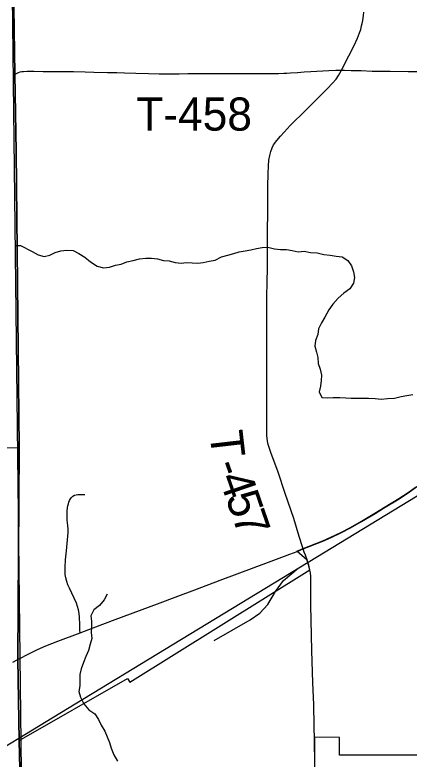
# Model space of a CAD drawing. Extents: x -7.5 to 53.5, y 0 to 22.
# Drawn here: x 4.57 to 5.246, y 17.086 to 18.362 of the extents above; entities that cross this region are included whole.
import ezdxf

# ---------------------------------------------------------------- set-up
doc = ezdxf.new("R2010")
doc.units = 0
for name, color, linetype in [('GM_X_Corporation', 7, 'Continuous'), ('GM_X_Minor_River', 7, 'Continuous'), ('GM_X_Rail_Line', 7, 'Continuous'), ('GM_X_State_Route', 7, 'Continuous'), ('GM_X_Township_Road', 7, 'Continuous'), ('GM_X_Township_Road_Text', 7, 'Continuous'), ('SH_Data', 7, 'Continuous')]:
    doc.layers.add(name, color=color, linetype=linetype)

msp = doc.modelspace()

# ---------------------------------------------------------------- linework, layer by layer
at = {"layer": 'GM_X_Corporation'}
for points in [[(4.6087, 14.5302), (4.6021, 15.6139), (4.594, 15.8096), (4.5873, 16.3533), (4.5872, 16.3635), (4.5826, 16.8462), (4.5822, 16.8992), (4.577, 17.1178), (4.5749, 17.2575), (4.5771, 17.6201), (4.5718, 18.1276), (4.5696, 18.2604), (4.5565, 19.1354), (5.0411, 19.1401), (6.0424, 19.1527), (6.0433, 19.1527), (6.5522, 19.1561), (7.544, 19.1455), (8.414, 19.1709), (8.5159, 19.1718), (8.9, 19.1887), (8.9, 20.9), (2.1, 20.9), (2.1, 14.1)], [(8.9, 14.1), (8.9, 19.1887), (8.5159, 19.1718), (8.414, 19.1709), (7.544, 19.1455), (6.5522, 19.1561), (6.0433, 19.1527), (6.0424, 19.1527), (5.0411, 19.1401), (4.5565, 19.1354), (4.5696, 18.2604), (4.5718, 18.1276), (4.5771, 17.6201), (4.5749, 17.2575), (4.577, 17.1178), (4.5822, 16.8992), (4.5826, 16.8462), (4.5872, 16.3635), (4.5873, 16.3533), (4.594, 15.8096), (4.6021, 15.6139), (4.6087, 14.5302)], [(4.1153, 17.6257), (4.5771, 17.6201), (4.5749, 17.2575), (4.577, 17.1178), (4.7631, 17.2246), (4.767, 17.2178), (5.0754, 17.4108), (5.0733, 17.4191), (5.0708, 17.4275), (5.0534, 17.4429), (5.064, 17.447), (5.0976, 17.4601), (5.1118, 17.4664), (5.1287, 17.4746), (5.1452, 17.4833), (5.1642, 17.4942), (5.1871, 17.508), (5.2017, 17.5167), (5.2283, 17.5331), (5.244, 17.5434), (5.2567, 17.5523)], [(5.4065, 17.093), (5.1262, 17.0931), (5.1262, 17.1234), (5.0833, 17.1238), (5.0837, 16.9694)]]:
    msp.add_lwpolyline(points, dxfattribs=at)
at = {"layer": 'GM_X_Minor_River'}
for points in [[(4.5699, 17.9665), (4.5794, 17.9668), (4.5997, 17.9567), (4.6099, 17.951), (4.6198, 17.9478), (4.6296, 17.9504), (4.6391, 17.9545), (4.6486, 17.9578), (4.6589, 17.9585), (4.6699, 17.958), (4.6797, 17.953), (4.6895, 17.9468), (4.6993, 17.9388), (4.711, 17.9311), (4.7215, 17.9283), (4.7318, 17.9298), (4.7424, 17.9331), (4.7519, 17.9345), (4.7618, 17.9386), (4.7724, 17.9408), (4.7835, 17.9437), (4.7941, 17.9451), (4.8039, 17.945), (4.8145, 17.9438), (4.8248, 17.9411), (4.8346, 17.9402), (4.8448, 17.9375), (4.8547, 17.9366), (4.8641, 17.9377), (4.874, 17.9368), (4.8835, 17.9367), (4.8929, 17.9374), (4.9032, 17.94), (4.9131, 17.9418), (4.9241, 17.9474), (4.9351, 17.9503), (4.945, 17.9533), (4.9545, 17.9558), (4.9644, 17.9576), (4.9746, 17.9594), (4.9841, 17.9616), (4.9936, 17.9634), (5.0038, 17.9637), (5.0148, 17.961), (5.025, 17.9597), (5.0353, 17.96), (5.0451, 17.958), (5.0553, 17.956), (5.0659, 17.9571), (5.0765, 17.9547), (5.0883, 17.9542), (5.0996, 17.9511), (5.1102, 17.9502), (5.1208, 17.9486), (5.1307, 17.9474), (5.1409, 17.9412), (5.1469, 17.9317), (5.1502, 17.9214), (5.152, 17.9119), (5.1504, 17.9021), (5.1439, 17.8923), (5.134, 17.8848), (5.1244, 17.8765), (5.1152, 17.8664), (5.1079, 17.8562), (5.101, 17.8441), (5.0956, 17.834), (5.0906, 17.8241), (5.089, 17.8143), (5.0855, 17.8041), (5.0843, 17.7939), (5.0869, 17.784), (5.0891, 17.7745), (5.0901, 17.7646), (5.0931, 17.7547), (5.0953, 17.7445), (5.0948, 17.735), (5.094, 17.7255), (5.0916, 17.7157), (5.0961, 17.7062), (5.1063, 17.7053), (5.1158, 17.706), (5.1272, 17.7059), (5.137, 17.7054), (5.1465, 17.7049), (5.1567, 17.7052), (5.1764, 17.705), (5.1874, 17.7046), (5.198, 17.7033), (5.2086, 17.7044), (5.2208, 17.705), (5.2322, 17.7076), (5.2417, 17.7094), (5.2523, 17.7112)], [(4.7279, 17.3689), (4.7229, 17.3591), (4.7149, 17.3493), (4.7053, 17.3418), (4.6999, 17.332), (4.7014, 17.3225), (4.7013, 17.3131), (4.7005, 17.3032), (4.7019, 17.2929), (4.6988, 17.2831), (4.696, 17.2725), (4.6914, 17.2619), (4.6875, 17.2517), (4.6837, 17.2412), (4.6813, 17.2313), (4.6812, 17.2215), (4.6811, 17.212), (4.6795, 17.2018), (4.6825, 17.1922), (4.6881, 17.1808), (4.6967, 17.1705), (4.7069, 17.164), (4.7133, 17.1541), (4.7177, 17.1445), (4.7241, 17.1339), (4.7278, 17.1243), (4.7323, 17.1144), (4.7352, 17.1049), (4.7393, 17.0935), (4.746, 17.0825)]]:
    msp.add_lwpolyline(points, dxfattribs=at)
at = {"layer": 'GM_X_Rail_Line'}
for points in [[(4.5767, 17.1219), (4.6471, 17.1649), (4.8554, 17.2917), (5.0726, 17.4239), (5.2728, 17.5456)], [(4.9114, 17.2896), (4.9735, 17.3249), (4.9899, 17.3362), (5.0034, 17.3512), (5.0168, 17.3736), (5.0302, 17.3923), (5.0555, 17.4135)], [(4.5236, 17.0903), (4.5767, 17.1219)]]:
    msp.add_lwpolyline(points, dxfattribs=at)
at = {"layer": 'GM_X_State_Route'}
for points in [[(5.0537, 17.4423), (5.0642, 17.4464), (5.0978, 17.4596), (5.112, 17.4659), (5.1289, 17.474), (5.1454, 17.4828), (5.1644, 17.4936), (5.1873, 17.5074), (5.2019, 17.5162), (5.2285, 17.5326), (5.2442, 17.5428), (5.2569, 17.5518), (5.2609, 17.5548), (5.2686, 17.561)], [(4.5751, 17.257), (4.5948, 17.2672), (4.6089, 17.2739), (4.6231, 17.2801), (4.6433, 17.2881), (4.6815, 17.3025), (4.7042, 17.3111), (4.7419, 17.3254), (4.8146, 17.3525), (4.8494, 17.3656), (4.8784, 17.3765), (4.922, 17.3929), (5.0091, 17.4255), (5.0411, 17.4374), (5.0537, 17.4423)], [(4.5663, 17.2522), (4.5739, 17.2564), (4.5751, 17.257)]]:
    msp.add_lwpolyline(points, dxfattribs=at)
at = {"layer": 'GM_X_Township_Road'}
for points in [[(5.1301, 18.2671), (5.1327, 18.2726), (5.1357, 18.279), (5.1422, 18.2918), (5.1507, 18.3084), (5.1573, 18.3225), (5.1608, 18.3312), (5.1628, 18.3371), (5.1644, 18.3432), (5.1654, 18.3471), (5.1664, 18.3526), (5.1677, 18.3613), (5.1683, 18.3666)], [(4.5698, 18.2599), (4.5735, 18.2623), (4.5758, 18.2634), (4.5787, 18.2644), (4.5817, 18.265), (4.5848, 18.2653), (4.5909, 18.2655), (4.6026, 18.2654), (4.6184, 18.2653), (4.6365, 18.2651), (4.6554, 18.265), (4.6704, 18.2648), (4.6902, 18.2647), (4.7052, 18.2642), (4.7287, 18.2635), (4.7449, 18.2631), (4.7577, 18.2627), (4.7771, 18.2621), (4.7987, 18.2615), (4.8172, 18.2613), (4.8265, 18.2612), (4.8513, 18.2613), (4.8664, 18.2614)], [(4.8664, 18.2614), (4.8855, 18.2615), (4.9072, 18.2616), (4.932, 18.2617), (4.9538, 18.2618), (4.9661, 18.2616), (4.9909, 18.2616), (5.0033, 18.2616), (5.0126, 18.2617), (5.0219, 18.2617), (5.0311, 18.262), (5.0362, 18.2624)], [(5.0088, 17.6117), (5.0073, 17.6155), (5.0043, 17.6256), (5.0029, 17.6314), (5.0016, 17.6409), (5.0016, 17.661), (5.0016, 17.6919), (5.0018, 17.731), (5.0019, 17.7547), (5.0019, 17.7935), (5.0019, 17.8774), (5.0023, 17.9049), (5.0027, 17.9276), (5.003, 17.9463), (5.003, 17.9572), (5.003, 17.9881), (5.0033, 18.0272), (5.0037, 18.0683), (5.0041, 18.0898), (5.0044, 18.1032), (5.0052, 18.1133), (5.0069, 18.1211), (5.0086, 18.1279), (5.0108, 18.1341), (5.0135, 18.1393), (5.0188, 18.1467), (5.0254, 18.1542), (5.0315, 18.1613), (5.0421, 18.1726), (5.0684, 18.1989), (5.0926, 18.2229), (5.1059, 18.2359), (5.1145, 18.2449), (5.1205, 18.252), (5.1246, 18.258), (5.1271, 18.262), (5.1301, 18.2671)], [(5.0362, 18.2624), (5.0422, 18.2628), (5.0542, 18.2636), (5.066, 18.2644), (5.0775, 18.2652), (5.1082, 18.2667), (5.1204, 18.2672), (5.1301, 18.2671)], [(5.1301, 18.2671), (5.135, 18.2671), (5.1462, 18.2669), (5.1634, 18.2666), (5.1823, 18.2659), (5.1863, 18.2659)], [(5.1863, 18.2659), (5.2133, 18.2658), (5.2444, 18.2652), (5.2816, 18.2649), (5.3406, 18.2643), (5.4183, 18.2635), (5.4555, 18.2634), (5.4897, 18.2638), (5.5052, 18.2636), (5.5145, 18.263), (5.5207, 18.2622), (5.5268, 18.261), (5.5327, 18.2592), (5.5385, 18.257), (5.5441, 18.2543), (5.5523, 18.2498), (5.5845, 18.2311), (5.6165, 18.2125), (5.6515, 18.1924), (5.7082, 18.1601), (5.7435, 18.1405), (5.7536, 18.1351)], [(5.0642, 17.4464), (5.063, 17.45), (5.0573, 17.468), (5.0481, 17.4986), (5.0335, 17.5417), (5.0213, 17.5784), (5.0088, 17.6117)], [(4.6815, 17.3025), (4.6813, 17.3075), (4.681, 17.3169), (4.6806, 17.3294), (4.68, 17.3356), (4.679, 17.3418), (4.6774, 17.3478), (4.6753, 17.3537), (4.6714, 17.3622), (4.6633, 17.3791), (4.6609, 17.3848), (4.6589, 17.3907), (4.6573, 17.3968), (4.6563, 17.4029), (4.6559, 17.4091), (4.6559, 17.4154), (4.6568, 17.4278), (4.6584, 17.4434), (4.6603, 17.462), (4.6613, 17.4744), (4.6613, 17.4806), (4.6608, 17.4867), (4.6597, 17.4959), (4.6594, 17.5021), (4.6595, 17.5114), (4.6601, 17.5176), (4.6607, 17.5206), (4.6615, 17.5237), (4.6625, 17.5266), (4.6637, 17.5295), (4.6653, 17.5322), (4.6671, 17.5346), (4.6694, 17.5367), (4.672, 17.5384), (4.6749, 17.5394), (4.678, 17.5398), (4.6809, 17.5401), (4.6841, 17.5401), (4.6898, 17.54)], [(5.0707, 17.4278), (5.068, 17.4358), (5.0661, 17.4411), (5.0642, 17.4464)], [(5.0756, 17.4103), (5.0752, 17.4121), (5.0736, 17.4186), (5.071, 17.4269), (5.0707, 17.4278)], [(5.0834, 17.1243), (5.0834, 17.1253), (5.0833, 17.1283), (5.0832, 17.1332), (5.0832, 17.1365), (5.0831, 17.1417), (5.083, 17.1463), (5.083, 17.1489), (5.083, 17.1521), (5.0828, 17.1551), (5.0827, 17.1581), (5.0825, 17.1642), (5.0822, 17.1797), (5.0809, 17.2167), (5.0792, 17.2722), (5.0777, 17.3245), (5.0774, 17.3498), (5.0774, 17.3603), (5.0773, 17.3794), (5.0773, 17.3919), (5.0772, 17.3993), (5.0765, 17.4054), (5.0756, 17.4103)], [(5.0839, 16.9689), (5.0839, 16.9888), (5.084, 16.9961), (5.084, 17.0058), (5.0841, 17.0141), (5.0842, 17.0233), (5.0843, 17.0368), (5.0844, 17.0475), (5.0844, 17.0541), (5.0844, 17.0598), (5.0843, 17.066), (5.0841, 17.0767), (5.084, 17.0858), (5.0839, 17.0941), (5.0838, 17.1028), (5.0837, 17.1094), (5.0836, 17.113), (5.0835, 17.1188), (5.0835, 17.1232), (5.0834, 17.1243)]]:
    msp.add_lwpolyline(points, dxfattribs=at)
at = {"layer": 'SH_Data'}
msp.add_lwpolyline([(8.9, 19.1896), (4.5566, 19.1336), (4.6149, 14.11), (4.6151, 14.1)], dxfattribs=at)

# ---------------------------------------------------------------- texts
at = {"layer": 'GM_X_Township_Road_Text'}
for s, height, rotation, p in [('T-458', 0.05682, 0, (4.7778, 18.1637)), ('T', 0.0568, 276.5499, (4.9034, 17.6464)), ('-', 0.0568, 289.4897, (4.9114, 17.5906)), ('4', 0.0568, 288.7723, (4.9191, 17.5688)), ('5', 0.0568, 288.9538, (4.9305, 17.5355)), ('7', 0.0568, 288.9875, (4.9419, 17.5023))]:
    msp.add_text(s, height=height, rotation=rotation, dxfattribs=at).set_placement(p)

doc.saveas('drawing.dxf')
